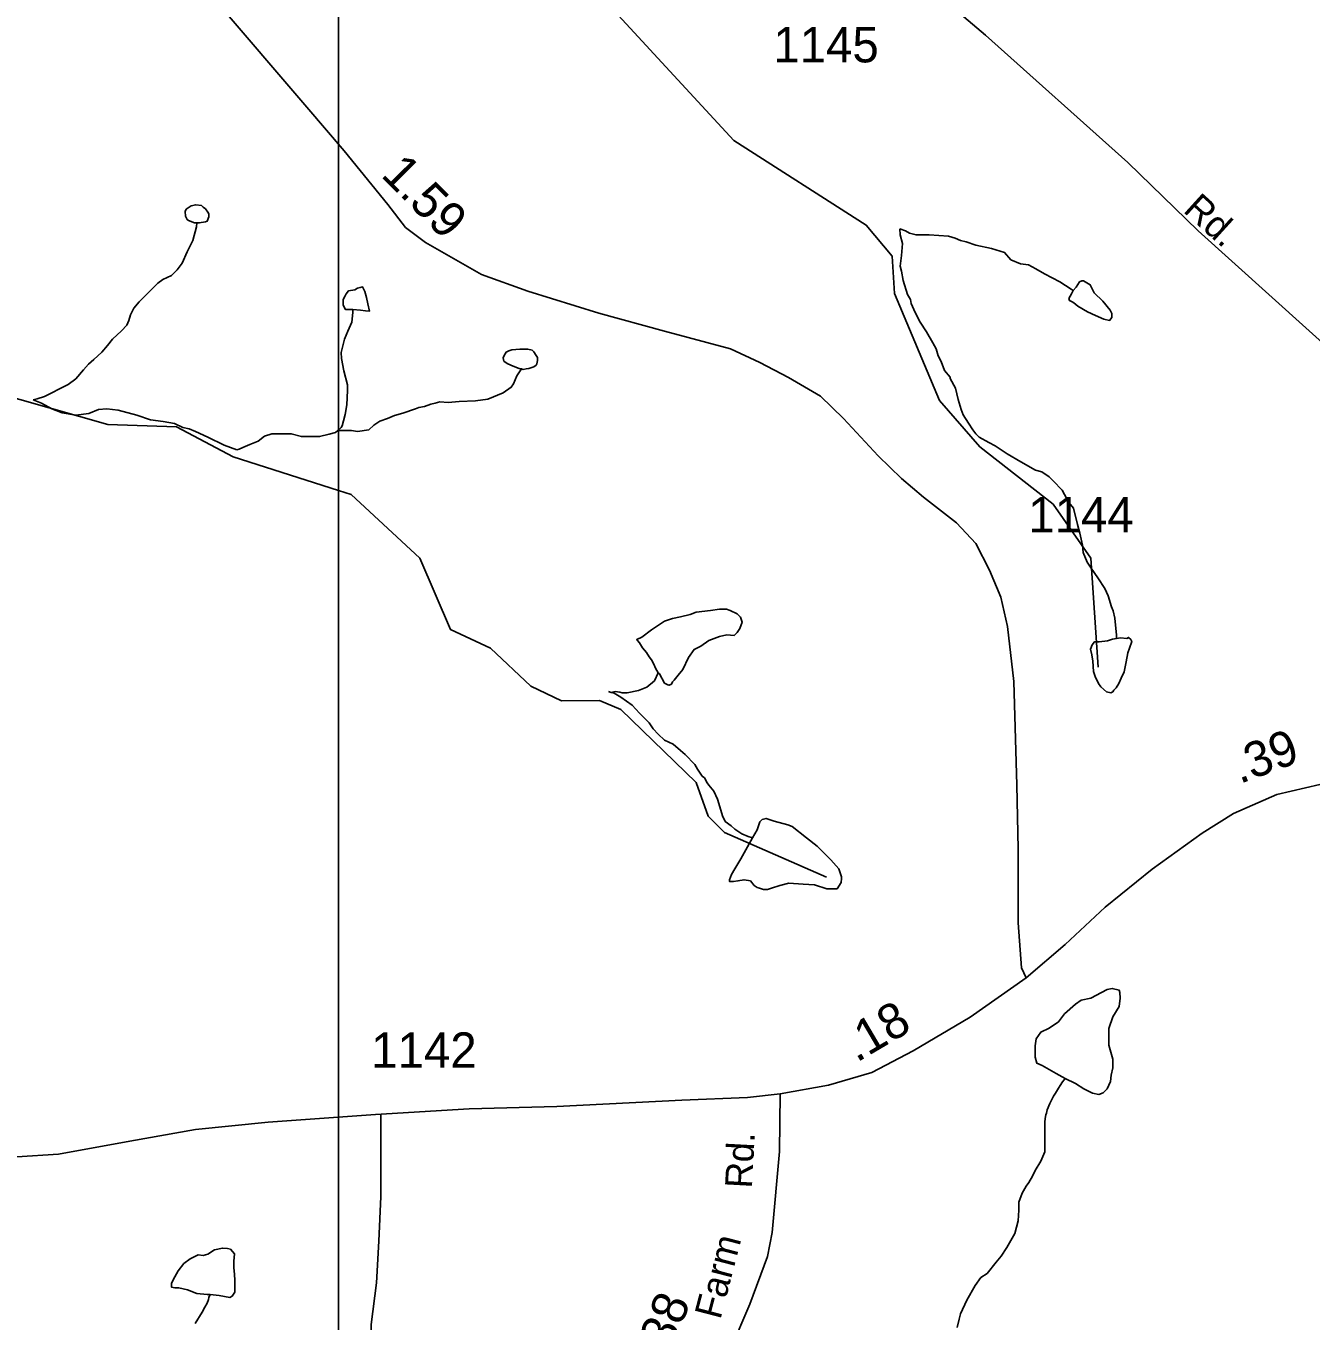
# Model space of a CAD drawing. Extents: x 2001466 to 2224147, y 644118 to 847247.
# Drawn here: x 2019370 to 2023901, y 709402 to 713970 of the extents above; entities that cross this region are included whole.
import ezdxf

# ---------------------------------------------------------------- set-up
doc = ezdxf.new("R2010")
doc.units = 0
for name, color, linetype in [('Exist Hydrographic Misc Water Feature', 7, 'Continuous'), ('Exist Road Non-System Type 51', 7, 'Continuous'), ('Exist Road Secondary Mileage Hundredths English Label', 7, 'Continuous'), ('Exist Road Secondary Type 41 Attributed', 7, 'Continuous'), ('Exist Road Secondary Type 51 Attributed', 7, 'Continuous'), ('Exist Road Secondary Type 51 Label', 7, 'Continuous'), ('Exist Road Secondary Type 51 Number Label', 7, 'Continuous'), ('Map Preparation Inset Cut Line', 7, 'Continuous')]:
    doc.layers.add(name, color=color, linetype=linetype)

msp = doc.modelspace()

# ---------------------------------------------------------------- linework, layer by layer
at = {"layer": 'Exist Hydrographic Misc Water Feature'}
for points in [[(2023150.9, 711708.5), (2023124.8, 712092.9), (2022992, 712282.7), (2022733.8, 712484.8), (2022591.9, 712648.5), (2022433, 713025.8), (2022425, 713157.1), (2022332.9, 713267.3), (2021866, 713565.6), (2021275.1, 714207.5), (2021090.9, 714555.8), (2021040.9, 714730.7), (2021040.1, 715180.2), (2020982.1, 715289.7), (2020957, 715556), (2021015.1, 715738.6), (2021207, 716131.7), (2021232, 716324.7), (2021356.1, 716614.2), (2021606, 717016)], [(2019973.4, 713274.8), (2019981.4, 713274.8), (2020003.5, 713278.8), (2020009.3, 713280.8), (2020015.4, 713296.8), (2020015.4, 713306.8), (2020011.3, 713312.8), (2020003.3, 713324.8), (2019995.3, 713330.8), (2019989.4, 713336.8), (2019969.3, 713338.8), (2019953.3, 713334.8), (2019935.5, 713322.8), (2019931.4, 713314.8), (2019933.4, 713298.8), (2019939.4, 713286.8), (2019943.5, 713282.8), (2019965.4, 713274.8), (2019973.4, 713274.8)], [(2019973.4, 713274.8), (2019971.6, 713260.8), (2019959.5, 713212.8), (2019939.4, 713172.8), (2019921.5, 713132.8), (2019903.5, 713108.8), (2019883.6, 713088.8), (2019853.7, 713074.8), (2019835.6, 713062.8), (2019809.6, 713036.8), (2019769.6, 712996.7), (2019751.5, 712974.7), (2019739.6, 712950.7), (2019733.7, 712930.7), (2019725.7, 712914.7), (2019707.7, 712894.7), (2019675.7, 712864.7), (2019657.6, 712842.7), (2019637.7, 712818.7), (2019609.6, 712792.7), (2019591.6, 712776.6), (2019573.8, 712756.6), (2019545.9, 712724.6), (2019519.8, 712704.6), (2019491.7, 712690.6), (2019459.7, 712674.6), (2019435.8, 712662.6), (2019409.7, 712654.5), (2019395.8, 712650.5)], [(2023063.1, 713036.7), (2023055.1, 713040.7), (2023015.1, 713066.6), (2022961, 713094.7), (2022931.1, 713112.7), (2022905, 713126.6), (2022877.1, 713130.6), (2022843.1, 713144.5), (2022821, 713170.6), (2022775, 713184.5), (2022719.1, 713196.5), (2022685, 713208.5), (2022665.1, 713212.5), (2022647.1, 713220.5), (2022623.1, 713228.5), (2022555, 713232.4), (2022521, 713232.3), (2022509.1, 713232.4), (2022485.1, 713238.3), (2022471.1, 713246.3), (2022451, 713254.3)], [(2023215.7, 711808.9), (2023215.7, 711821), (2023209.7, 711881), (2023203.8, 711906.9), (2023197.8, 711920.9), (2023185.5, 711959), (2023173.7, 711984.9), (2023149.7, 712022.9), (2023125.7, 712056.9), (2023111.7, 712078.8), (2023097.6, 712112.8), (2023095.7, 712138.8), (2023085.7, 712180.8), (2023077.5, 712210.8), (2023063.5, 712268.8), (2023047.5, 712288.8), (2023023.6, 712332.8), (2022991.6, 712364.8), (2022977.6, 712378.7), (2022951.6, 712396.7), (2022929.4, 712402.7), (2022877.6, 712432.7), (2022829.6, 712460.6), (2022787.3, 712488.6), (2022765.4, 712500.6), (2022731.4, 712518.6), (2022719.5, 712530.6), (2022709.4, 712544.6), (2022693.4, 712568.5), (2022675.4, 712598.5), (2022667.4, 712616.5), (2022657.3, 712652.5), (2022647.5, 712692.5), (2022629.4, 712726.5), (2022629.2, 712730.5), (2022609.3, 712754.4), (2022597.3, 712786.5), (2022587.2, 712806.5), (2022579.2, 712830.5), (2022567.3, 712852.4), (2022545.4, 712890.4), (2022523.2, 712924.4), (2022505.4, 712958.4), (2022491.2, 712990.4), (2022489.2, 713004.4), (2022479.1, 713022.4), (2022463.1, 713072.3), (2022457.2, 713104.3), (2022453.1, 713122.3), (2022457.2, 713160.3), (2022461.1, 713202.3), (2022453.1, 713232.3), (2022451, 713254.3)], [(2020472.9, 712330.8), (2020100.9, 712449.8), (2019901, 712555.6), (2019658.9, 712563.8), (2018926, 712772.4), (2018634, 712896.4), (2018441.9, 713021.8), (2018356.4, 713049.4)], [(2020523.4, 712969.2), (2020497.5, 712969.2), (2020489.5, 712985.2), (2020489.5, 713005.2), (2020495.5, 713017.2), (2020499.4, 713025.1), (2020507.4, 713035.1), (2020529.5, 713039.1), (2020539.3, 713045.1), (2020549.4, 713047.2), (2020557.4, 713049.2), (2020565.4, 713033.1), (2020571.5, 713011.2), (2020575.4, 712989.2), (2020581.4, 712963.2), (2020567.6, 712965.2), (2020549.6, 712967.2), (2020523.4, 712969.2)], [(2023063.1, 713036.7), (2023073, 713048.7), (2023085.3, 713066.7), (2023093.1, 713070.7), (2023099.2, 713070.7), (2023123, 713056.8), (2023136.9, 713028.7), (2023167.1, 712998.7), (2023193.1, 712966.8), (2023199.1, 712954.8), (2023199.1, 712946.8), (2023199.1, 712940.8), (2023191.1, 712930.8), (2023171.2, 712934.8), (2023141.3, 712948.8), (2023113.2, 712960.8), (2023079.1, 712980.7), (2023065.2, 712992.7), (2023059.2, 712996.7), (2023049.2, 713000.7), (2023047.1, 713008.7), (2023057.2, 713024.7), (2023063.1, 713036.7)], [(2020523.4, 712969.2), (2020523.6, 712959.2), (2020519.7, 712925.2), (2020505.5, 712893.2), (2020493.6, 712865.2), (2020481.5, 712817.2), (2020483.6, 712797.2), (2020491.8, 712753.1), (2020503.7, 712703.2), (2020503.7, 712683.2), (2020501.6, 712633.2), (2020495.7, 712599.2), (2020489.7, 712577.2), (2020485.6, 712559.2), (2020481.7, 712553.2), (2020469.8, 712543.2)], [(2021117.6, 712759.6), (2021109.6, 712761.6), (2021093.6, 712767.6), (2021079.7, 712773.5), (2021067.6, 712779.5), (2021055.5, 712787.5), (2021053.6, 712799.5), (2021057.5, 712809.5), (2021059.6, 712813.5), (2021063.5, 712819.5), (2021073.5, 712823.5), (2021083.6, 712827.5), (2021111.6, 712829.5), (2021139.5, 712829.6), (2021155.5, 712825.6), (2021161.5, 712819.6), (2021169.5, 712807.6), (2021173.6, 712799.6), (2021173.6, 712789.6), (2021171.5, 712777.6), (2021169.5, 712773.6), (2021161.5, 712767.6), (2021143.6, 712761.6), (2021133.6, 712759.6), (2021123.5, 712757.6), (2021117.6, 712759.6)], [(2021117.6, 712759.6), (2021101.6, 712735.6), (2021089.5, 712707.5), (2021081.5, 712695.5), (2021053.6, 712675.5), (2020999.5, 712653.5), (2020955.6, 712647.5), (2020897.8, 712645.5), (2020859.6, 712641.4), (2020829.7, 712643.4), (2020813.7, 712639.4), (2020797.7, 712635.4), (2020775.8, 712627.3), (2020755.7, 712623.3), (2020743.6, 712619.4), (2020699.7, 712603.4), (2020669.8, 712595.3), (2020645.8, 712585.3), (2020617.7, 712575.3), (2020597.6, 712561.3), (2020579.7, 712545.3), (2020539.8, 712539.2), (2020517.8, 712543.2), (2020483.8, 712543.2), (2020469.8, 712543.2)], [(2020113.9, 712474.9), (2020069.8, 712491), (2020011.7, 712519), (2019967.9, 712538.9), (2019945.7, 712548.9), (2019923.8, 712552.9), (2019893.8, 712566.9), (2019853.9, 712574.9), (2019809.8, 712580.8), (2019761.8, 712596.8), (2019695.8, 712614.7), (2019655.8, 712618.7), (2019625.8, 712616.6), (2019591.8, 712602.6), (2019545.9, 712596.6), (2019497.9, 712604.6), (2019461.8, 712618.6), (2019425.9, 712638.6), (2019395.8, 712650.5)], [(2020469.8, 712543.2), (2020461.8, 712535.2), (2020439.9, 712529.2), (2020405.9, 712521.2), (2020377.8, 712521.2), (2020341.9, 712521.2), (2020305.8, 712531.1), (2020267.9, 712531.1), (2020237.7, 712531.1), (2020211.9, 712523), (2020189.7, 712505), (2020159.8, 712493), (2020135.8, 712483), (2020121.9, 712477), (2020113.9, 712474.9)], [(2022192.9, 710966.8), (2021833.8, 711125), (2021775.8, 711182), (2021734, 711301), (2021467.8, 711559), (2021393, 711590.1), (2021258.9, 711589.5), (2021150.8, 711641), (2021008.9, 711775.1), (2020867.8, 711840.4), (2020759, 712091.9), (2020517, 712316.6), (2020472.9, 712330.8)], [(2021600.1, 711688), (2021590, 711704), (2021584.1, 711718), (2021576.1, 711734), (2021568.1, 711744), (2021558, 711759.9), (2021544.1, 711775.9), (2021534.1, 711793.9), (2021526.1, 711801.9), (2021524, 711805.9), (2021542.1, 711813.9), (2021576.1, 711840), (2021622, 711870), (2021650.1, 711880), (2021678, 711886), (2021711.8, 711894.1), (2021734, 711902.1), (2021783.8, 711908.1), (2021816, 711912.1), (2021840, 711912.1), (2021853.9, 711908.1), (2021877.9, 711896.1), (2021889.8, 711884.1), (2021896, 711866.1), (2021888, 711844.1), (2021877.9, 711830.1), (2021867.9, 711820.1), (2021842, 711822.1), (2021816, 711816.1), (2021778.1, 711802.1), (2021750, 711782.1), (2021726, 711770.1), (2021706.1, 711742), (2021686, 711700.1), (2021670, 711680.1), (2021656.1, 711662), (2021650.1, 711656.1), (2021646.2, 711648), (2021638.2, 711644), (2021634.1, 711646.1), (2021622, 711652), (2021604, 711684), (2021600.1, 711688)], [(2023215.7, 711808.9), (2023229.8, 711810.9), (2023251.8, 711808.9), (2023257.7, 711813), (2023265.7, 711805), (2023269.8, 711799), (2023261.8, 711774.9), (2023255.7, 711759), (2023249.9, 711727), (2023241.9, 711691), (2023231.9, 711669), (2023223.9, 711650.9), (2023213.8, 711634.9), (2023205.8, 711627), (2023201.9, 711621), (2023195.8, 711617), (2023179.8, 711621), (2023159.9, 711638.9), (2023151.9, 711650.9), (2023139.8, 711674.9), (2023133.9, 711692.9), (2023131.8, 711728.9), (2023127.9, 711750.9), (2023123.8, 711770.9), (2023130, 711786.9), (2023137.8, 711796.9), (2023153.8, 711796.9), (2023183.7, 711800.9), (2023201.7, 711806.9), (2023215.7, 711808.9)], [(2021600.1, 711688), (2021586.1, 711660), (2021560.1, 711638), (2021530.2, 711626), (2021490.2, 711617.9), (2021472.1, 711617.9), (2021464.1, 711619.9), (2021448.1, 711621.9), (2021433.4, 711619.1), (2021424.1, 711621.9)], [(2021932.5, 711106.3), (2021916.5, 711110.3), (2021894.3, 711120.3), (2021870.3, 711136.3), (2021856.4, 711148.3), (2021836.3, 711164.2), (2021826.5, 711184.2), (2021820.3, 711204.2), (2021808.2, 711242.2), (2021796.3, 711270.2), (2021778.3, 711292.1), (2021772.3, 711300.1), (2021762.3, 711318.1), (2021754.3, 711324.1), (2021738.3, 711348.1), (2021728.2, 711364.1), (2021694.2, 711400.1), (2021678.2, 711414.1), (2021652.2, 711436), (2021622.2, 711450), (2021600.1, 711472), (2021582.2, 711490), (2021568.1, 711512), (2021534.1, 711546), (2021508.2, 711573.9), (2021468.2, 711601.9), (2021444.2, 711615.9), (2021433.4, 711619.1), (2021424.1, 711621.9)], [(2021932.5, 711106.3), (2021948.5, 711134.3), (2021958.3, 711162.3), (2021966.3, 711170.3), (2021980.2, 711174.3), (2022008.3, 711164.3), (2022056.3, 711152.4), (2022072.3, 711146.4), (2022122.4, 711106.4), (2022160.3, 711076.4), (2022208.5, 711028.5), (2022236.4, 710996.4), (2022246.4, 710968.5), (2022246.4, 710962.4), (2022244.4, 710948.4), (2022230.4, 710926.5), (2022194.3, 710926.4), (2022150.4, 710940.4), (2022110.5, 710942.4), (2022060.4, 710946.4), (2022028.4, 710938.4), (2021998.5, 710928.4), (2021984.6, 710924.3), (2021970.4, 710924.3), (2021956.5, 710928.3), (2021948.5, 710930.3), (2021938.4, 710938.3), (2021924.5, 710954.3), (2021902.5, 710958.3), (2021880.6, 710954.2), (2021864.6, 710952.2), (2021854.6, 710952.2), (2021850.5, 710952.2), (2021850.5, 710958.2), (2021858.4, 710976.3), (2021870.3, 710996.3), (2021890.4, 711032.2), (2021932.5, 711106.3)], [(2023034.6, 710257.1), (2023002.6, 710275), (2022952.8, 710303), (2022934.6, 710310.9), (2022928.6, 710333), (2022928.6, 710353), (2022928.6, 710373), (2022932.5, 710396.9), (2022948.5, 710420.9), (2022978.6, 710434.9), (2023010.6, 710457), (2023032.6, 710485), (2023070.5, 710519), (2023090.4, 710533), (2023124.4, 710541.1), (2023162.6, 710561.1), (2023182.5, 710571.1), (2023200.5, 710575.1), (2023224.5, 710569.1), (2023226.6, 710561.1), (2023228.4, 710541.1), (2023224.5, 710511.2), (2023202.6, 710475.1), (2023188.6, 710433.1), (2023188.6, 710409.1), (2023188.6, 710375.2), (2023202.6, 710325.1), (2023202.6, 710295.1), (2023196.6, 710269.1), (2023194.6, 710247.2), (2023182.7, 710221.2), (2023168.7, 710207.1), (2023152.7, 710201.1), (2023130.8, 710205.1), (2023100.7, 710221.1), (2023070.7, 710239.1), (2023034.6, 710257.1)], [(2022970.7, 710147), (2022980.7, 710169), (2022992.8, 710195), (2023000.8, 710205), (2023010.6, 710223), (2023016.8, 710233), (2023024.8, 710245.1), (2023030.7, 710253), (2023034.6, 710257.1)], [(2022653.2, 709379), (2022661.2, 709409), (2022665.1, 709426.9), (2022687.3, 709474.9), (2022717, 709527), (2022737.1, 709554.9), (2022759, 709569), (2022791, 709609), (2022809.1, 709631), (2022829.2, 709661), (2022857.1, 709711), (2022868.9, 709755), (2022871, 709793), (2022871, 709821), (2022882.9, 709853), (2022897, 709877), (2022906.9, 709891), (2022918.8, 709913), (2022928.8, 709933), (2022948.9, 709965.1), (2022962.9, 709999.1), (2022962.9, 710033), (2022962.9, 710069), (2022962.9, 710093), (2022962.7, 710105), (2022964.7, 710123), (2022966.8, 710129), (2022968.8, 710135), (2022970.7, 710147)], [(2020019.5, 709495.3), (2020009.5, 709495.3), (2019973.4, 709499.3), (2019939.6, 709511.3), (2019909.4, 709519.2), (2019895.5, 709519.2), (2019883.4, 709521.3), (2019883.4, 709535.2), (2019895.5, 709557.2), (2019907.4, 709579.2), (2019927.5, 709605.2), (2019949.4, 709621.3), (2019977.5, 709635.3), (2019995.5, 709633.3), (2020011.5, 709637.3), (2020035.5, 709653.3), (2020063.4, 709659.3), (2020081.5, 709657.3), (2020091.5, 709655.3), (2020105.5, 709639.3), (2020103.4, 709613.3), (2020103.4, 709589.3), (2020105.5, 709567.4), (2020107.5, 709545.3), (2020107.5, 709525.4), (2020107.5, 709503.3), (2020097.5, 709489.3), (2020089.5, 709485.3), (2020051.5, 709491.3), (2020019.5, 709495.3)], [(2019967.7, 709393.3), (2019991.7, 709433.4), (2020001.5, 709451.3), (2020009.5, 709465.3), (2020013.6, 709477.3), (2020015.6, 709485.3), (2020019.5, 709495.3)]]:
    msp.add_lwpolyline(points, dxfattribs=at)
at = {"layer": 'Exist Road Non-System Type 51'}
msp.add_lwpolyline([(2020621.8, 710131.7), (2020621.8, 709841.3), (2020614.2, 709683.1), (2020606.7, 709536.2), (2020587.9, 709389.2), (2020587.9, 709227.3), (2020569.1, 709095.4), (2020576.6, 708974.9), (2020557.8, 708892), (2020557.8, 708846.8), (2020554, 708763.9), (2020546.5, 708718.7), (2020535.2, 708684.8), (2020523.9, 708650.9), (2020493.8, 708601.9)], dxfattribs=at)
at = {"layer": 'Exist Road Secondary Type 41 Attributed'}
msp.add_lwpolyline([(2022029.6, 710203.3), (2022027.2, 709999.7), (2022001.7, 709713.9), (2021985.3, 709629.3), (2021923.1, 709460.9), (2021853.3, 709299.6), (2021801.5, 709194.2), (2021780.7, 709136.8), (2021764.8, 709025), (2021753.6, 708879.7), (2021771.5, 708681.7), (2021808.2, 708627.5), (2021895.6, 708575.6), (2022014.4, 708534.1), (2022101.4, 708506.1), (2022187.2, 708427.9)], dxfattribs=at)
at = {"layer": 'Exist Road Secondary Type 51 Attributed'}
for points in [[(2022070.2, 717279.8), (2022032.4, 717115.6), (2021952.2, 716840.2), (2021874.8, 716560.8), (2021825.8, 716335.7), (2021814.6, 716257.5), (2021847.3, 716024.4), (2021913.1, 715613.2), (2022001.7, 715041.7), (2022036.8, 714744.7), (2022055.9, 714577.1), (2022090.2, 714492.5), (2022181.2, 714396.7), (2022433.3, 714209.9), (2022753.1, 713936.8), (2023255.7, 713488.2), (2023503, 713247.1), (2024143.6, 712669.2), (2024555.2, 712303.6), (2024717.6, 712151.1)], [(2022896.7, 710612.8), (2022881, 710647.1), (2022868.4, 710806.1), (2022868.8, 711067), (2022864.4, 711291.3), (2022853.3, 711656.9), (2022830.6, 711851), (2022807.9, 711954.4), (2022767.5, 712050.3), (2022719.6, 712143.7), (2022651.5, 712216.9), (2022535.5, 712307.8), (2022457.3, 712373.4), (2022375.1, 712453.1), (2022252.4, 712584.9), (2022172.2, 712663.6), (2022058.7, 712729.2), (2021957.8, 712782.2), (2021854.4, 712830.2), (2021622.3, 712893.3), (2021390.2, 712956.4), (2021140.5, 713034.6), (2020976.5, 713092.7), (2020779.8, 713206.2), (2020709.1, 713259.2), (2020646.1, 713340), (2020492.2, 713529.3), (2020361, 713683.2), (2020038.1, 714061.8)], [(2024702, 711443), (2024609.5, 711451.8), (2024513.7, 711437.4), (2024349, 711396.7), (2024084.2, 711329.7), (2023781, 711259.4), (2023627.9, 711192.3), (2023517, 711122.1), (2023341.1, 710995.2), (2023175.1, 710861.1), (2023034.7, 710730.1), (2022896.7, 710612.8)], [(2022896.7, 710612.8), (2022699.3, 710473.1), (2022498.3, 710355), (2022353.1, 710278.3), (2022199.9, 710233.6), (2022029.6, 710203.3)], [(2022029.6, 710203.3), (2021913.9, 710189.7), (2021683, 710180.9), (2021241.8, 710158.6), (2020933.5, 710149.8), (2020603.3, 710130.6), (2020224.3, 710102.7), (2019968.7, 710077.9), (2019737.3, 710036.4), (2019485.2, 709990.1), (2019338.5, 709980.6), (2019216.4, 709982.9), (2019122.3, 710000.5), (2019023.4, 710044.4), (2018889.7, 710129), (2018766.1, 710184.9), (2018639.2, 710242.4), (2018521.2, 710269.5), (2018371.6, 710287.1), (2018133.9, 710301.5), (2017893, 710299.9), (2017715.7, 710305.3)]]:
    msp.add_lwpolyline(points, dxfattribs=at)
at = {"layer": 'Map Preparation Inset Cut Line'}
for p, q in [((2020472.9, 713518.1), (2020472.9, 717558.8)), ((2020472.9, 712330.8), (2020472.9, 713518.1)), ((2020472.9, 710121.8), (2020472.9, 712330.8)), ((2020472.9, 706915.1), (2020472.9, 710121.8))]:
    msp.add_line(p, q, dxfattribs=at)

# ---------------------------------------------------------------- texts
at = {"layer": 'Exist Road Secondary Mileage Hundredths English Label'}
for s, rotation, p in [('1.59', 314.7854, (2020618.6, 713441.2)), ('.39', 20.3475, (2023649.7, 711295.5)), ('.18', 30.4881, (2022299, 710312.1)), ('.38', 68.0397, (2021628.2, 709253.7))]:
    msp.add_text(s, height=125, rotation=rotation, dxfattribs=at).set_placement(p)
at = {"layer": 'Exist Road Secondary Type 51 Label'}
for s, rotation, p in [('Rd.', 317.8119, (2023447, 713316)), ('Rd.', 86.9279, (2021929.8, 709868.3)), ('Farm', 75.4087, (2021818.6, 709404.2))]:
    msp.add_text(s, height=95, rotation=rotation, dxfattribs=at).set_placement(p)
at = {"layer": 'Exist Road Secondary Type 51 Number Label'}
for s, p in [('1145', (2022005.4, 713841)), ('1144', (2022904.3, 712183.3)), ('1142', (2020587.8, 710294.9))]:
    msp.add_text(s, height=125, dxfattribs=at).set_placement(p)

doc.saveas('drawing.dxf')
